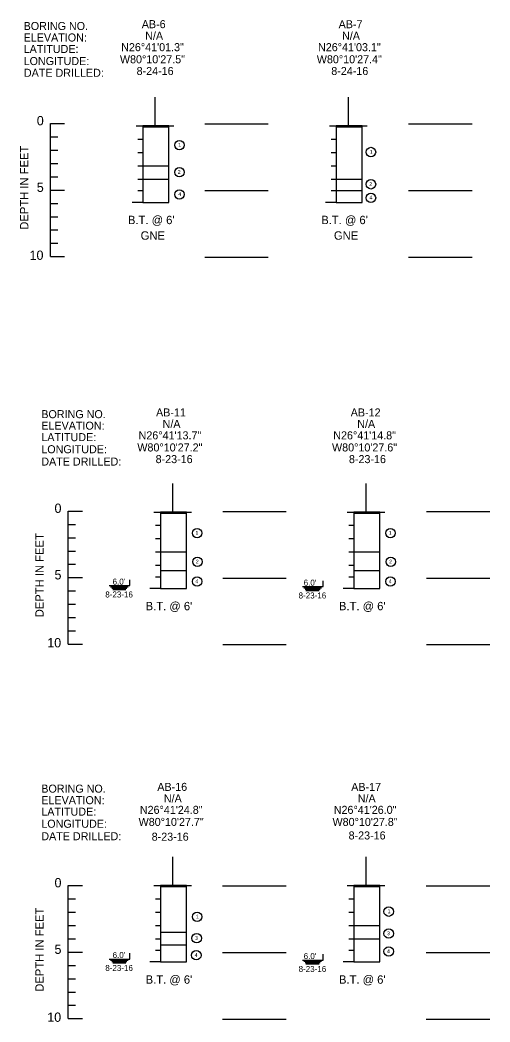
# Model space of a CAD drawing. Extents: x 0 to 331, y -72 to 117.
# Drawn here: x 74.02 to 92.94, y -21.91 to 18.43 of the extents above; entities that cross this region are included whole.
import ezdxf

# ---------------------------------------------------------------- set-up
doc = ezdxf.new("R2010")
doc.units = 0
for name, color, linetype in [('1-BORE', 7, 'Continuous'), ('1-GRID', 7, 'Continuous'), ('1-TEXT', 7, 'Continuous')]:
    doc.layers.add(name, color=color, linetype=linetype)

msp = doc.modelspace()

# ---------------------------------------------------------------- linework, layer by layer
at = {"layer": '1-BORE'}
for p, q in [((78.97, 14.122), (80.015, 14.122)), ((86.75, 14.122), (87.795, 14.122)), ((78.97, 12.556), (80.015, 12.556)), ((78.97, 12.556), (80.015, 12.556)), ((78.97, 12.02), (80.015, 12.02)), ((78.97, 12.02), (80.015, 12.02)), ((86.75, 12.02), (87.795, 12.02)), ((86.75, 12.02), (87.795, 12.02)), ((86.75, 11.557), (87.795, 11.557)), ((86.75, 11.557), (87.795, 11.557)), ((78.97, 11.083), (78.541, 11.083)), ((78.97, 11.083), (80.015, 11.083)), ((86.75, 11.083), (86.322, 11.083)), ((86.75, 11.083), (87.795, 11.083)), ((79.682, -1.422), (80.727, -1.422)), ((87.462, -1.422), (88.507, -1.422)), ((79.682, -2.989), (80.727, -2.989)), ((79.682, -2.989), (80.727, -2.989)), ((87.462, -2.989), (88.507, -2.989)), ((87.462, -2.989), (88.507, -2.989)), ((79.682, -3.739), (80.727, -3.739)), ((79.682, -3.739), (80.727, -3.739)), ((87.462, -3.739), (88.507, -3.739)), ((87.462, -3.739), (88.507, -3.739)), ((79.682, -4.462), (79.254, -4.462)), ((79.682, -4.462), (80.727, -4.462)), ((87.462, -4.462), (87.034, -4.462)), ((87.462, -4.462), (88.507, -4.462)), ((79.682, -16.459), (80.727, -16.459)), ((87.462, -16.459), (88.507, -16.459)), ((87.462, -18.025), (88.507, -18.025)), ((87.462, -18.025), (88.507, -18.025)), ((79.682, -18.3), (80.727, -18.3)), ((79.682, -18.3), (80.727, -18.3)), ((79.682, -18.802), (80.727, -18.802)), ((79.682, -18.802), (80.727, -18.802)), ((87.462, -18.561), (88.507, -18.561)), ((87.462, -18.561), (88.507, -18.561)), ((79.682, -19.498), (79.254, -19.498)), ((79.682, -19.498), (80.727, -19.498)), ((87.462, -19.498), (87.034, -19.498)), ((87.462, -19.498), (88.507, -19.498))]:
    msp.add_line(p, q, dxfattribs=at)
for points in [[(80.015, 14.122), (80.015, 14.164), (78.97, 14.164), (78.97, 14.122), (80.015, 14.122), (80.015, 14.122)], [(80.015, 11.083), (80.015, 14.164), (78.97, 14.164), (78.97, 11.083)], [(87.795, 14.122), (87.795, 14.164), (86.75, 14.164), (86.75, 14.122), (87.795, 14.122), (87.795, 14.122)], [(87.795, 11.083), (87.795, 14.164), (86.75, 14.164), (86.75, 11.083)], [(80.727, -4.462), (80.727, -1.381), (79.682, -1.381), (79.682, -4.462)], [(80.727, -1.422), (80.727, -1.381), (79.682, -1.381), (79.682, -1.422), (80.727, -1.422), (80.727, -1.422)], [(88.507, -4.462), (88.507, -1.381), (87.462, -1.381), (87.462, -4.462)], [(88.507, -1.422), (88.507, -1.381), (87.462, -1.381), (87.462, -1.422), (88.507, -1.422), (88.507, -1.422)], [(80.727, -19.498), (80.727, -16.418), (79.682, -16.418), (79.682, -19.498)], [(80.727, -16.459), (80.727, -16.418), (79.682, -16.418), (79.682, -16.459), (80.727, -16.459), (80.727, -16.459)], [(88.507, -19.498), (88.507, -16.418), (87.462, -16.418), (87.462, -19.498)], [(88.507, -16.459), (88.507, -16.418), (87.462, -16.418), (87.462, -16.459), (88.507, -16.459), (88.507, -16.459)]]:
    msp.add_lwpolyline(points, dxfattribs=at)
at = {"layer": '1-GRID'}
for p, q in [((75.254, 14.259), (75.819, 14.259)), ((81.462, 14.241), (84.016, 14.241)), ((89.662, 14.241), (92.216, 14.241)), ((75.254, 13.724), (75.539, 13.724)), ((78.765, 13.628), (78.97, 13.628)), ((86.545, 13.628), (86.75, 13.628)), ((75.254, 13.188), (75.539, 13.188)), ((78.765, 13.092), (78.97, 13.092)), ((86.545, 13.092), (86.75, 13.092)), ((75.254, 12.652), (75.539, 12.652)), ((78.765, 12.556), (78.97, 12.556)), ((86.545, 12.556), (86.75, 12.556)), ((75.254, 12.116), (75.539, 12.116)), ((78.765, 12.02), (78.97, 12.02)), ((86.545, 12.02), (86.75, 12.02)), ((75.254, 11.58), (75.819, 11.58)), ((75.254, 11.58), (75.819, 11.58)), ((78.765, 11.557), (78.97, 11.557)), ((81.462, 11.562), (84.016, 11.562)), ((86.545, 11.557), (86.75, 11.557)), ((89.662, 11.562), (92.216, 11.562)), ((75.254, 11.044), (75.539, 11.044)), ((78.97, 11.083), (79.174, 11.083)), ((86.75, 11.083), (86.955, 11.083)), ((75.254, 10.508), (75.539, 10.508)), ((75.254, 9.973), (75.539, 9.973)), ((75.254, 9.437), (75.539, 9.437)), ((75.254, 8.901), (75.819, 8.901)), ((81.462, 8.882), (84.016, 8.882)), ((89.662, 8.882), (92.216, 8.882)), ((75.966, -1.344), (76.531, -1.344)), ((75.966, -1.344), (76.531, -1.344)), ((82.183, -1.362), (84.737, -1.362)), ((90.384, -1.362), (92.938, -1.362)), ((75.966, -1.88), (76.251, -1.88)), ((79.477, -1.917), (79.682, -1.917)), ((87.258, -1.917), (87.462, -1.917)), ((75.966, -2.416), (76.251, -2.416)), ((79.477, -2.453), (79.682, -2.453)), ((87.258, -2.453), (87.462, -2.453)), ((75.966, -2.952), (76.251, -2.952)), ((79.477, -2.989), (79.682, -2.989)), ((87.258, -2.989), (87.462, -2.989)), ((75.966, -3.487), (76.251, -3.487)), ((79.477, -3.525), (79.682, -3.525)), ((87.258, -3.525), (87.462, -3.525)), ((75.966, -4.023), (76.531, -4.023)), ((75.966, -4.023), (76.531, -4.023)), ((79.477, -3.988), (79.682, -3.988)), ((87.258, -3.988), (87.462, -3.988)), ((82.183, -4.042), (84.737, -4.042)), ((90.384, -4.042), (92.938, -4.042)), ((75.966, -4.559), (76.251, -4.559)), ((79.682, -4.462), (79.887, -4.462)), ((87.462, -4.462), (87.667, -4.462)), ((75.966, -5.095), (76.251, -5.095)), ((75.966, -5.631), (76.251, -5.631)), ((75.966, -6.167), (76.251, -6.167)), ((75.966, -6.703), (76.531, -6.703)), ((82.183, -6.721), (84.737, -6.721)), ((90.384, -6.721), (92.938, -6.721)), ((75.966, -16.419), (76.531, -16.419)), ((75.966, -16.419), (76.531, -16.419)), ((82.175, -16.437), (84.729, -16.437)), ((90.374, -16.437), (92.928, -16.437)), ((75.966, -16.955), (76.251, -16.955)), ((79.477, -16.954), (79.682, -16.954)), ((87.258, -16.954), (87.462, -16.954)), ((75.966, -17.491), (76.251, -17.491)), ((79.477, -17.489), (79.682, -17.489)), ((87.258, -17.489), (87.462, -17.489)), ((75.966, -18.026), (76.251, -18.026)), ((79.477, -18.025), (79.682, -18.025)), ((87.258, -18.025), (87.462, -18.025)), ((75.966, -18.562), (76.251, -18.562)), ((79.477, -18.561), (79.682, -18.561)), ((87.258, -18.561), (87.462, -18.561)), ((75.966, -19.098), (76.531, -19.098)), ((75.966, -19.098), (76.531, -19.098)), ((79.477, -19.024), (79.682, -19.024)), ((82.175, -19.116), (84.729, -19.116)), ((87.258, -19.024), (87.462, -19.024)), ((90.374, -19.116), (92.928, -19.116)), ((75.966, -19.634), (76.251, -19.634)), ((79.682, -19.498), (79.887, -19.498)), ((87.462, -19.498), (87.667, -19.498)), ((75.966, -20.17), (76.251, -20.17)), ((75.966, -20.706), (76.251, -20.706)), ((75.966, -21.242), (76.251, -21.242)), ((75.966, -21.777), (76.531, -21.777)), ((82.175, -21.796), (84.729, -21.796)), ((90.374, -21.796), (92.928, -21.796))]:
    msp.add_line(p, q, dxfattribs=at)
for points in [[(75.254, 11.58), (75.254, 14.259)], [(75.254, 8.901), (75.254, 11.58)], [(75.966, -4.023), (75.966, -1.344)], [(75.966, -6.703), (75.966, -4.023)], [(75.966, -19.098), (75.966, -16.419)], [(75.966, -21.777), (75.966, -19.098)]]:
    msp.add_lwpolyline(points, dxfattribs=at)
at = {"layer": '1-TEXT'}
for p, q in [((79.449, 15.314), (79.449, 14.164)), ((87.23, 15.314), (87.23, 14.164)), ((80.162, -0.23), (80.162, -1.381)), ((87.942, -0.23), (87.942, -1.381)), ((77.612, -4.343), (78.437, -4.343)), ((77.666, -4.392), (78.376, -4.392)), ((78.437, -4.343), (78.437, -4.107)), ((85.392, -4.384), (86.218, -4.384)), ((85.447, -4.433), (86.157, -4.433)), ((86.218, -4.384), (86.218, -4.148)), ((77.714, -4.441), (78.32, -4.441)), ((77.752, -4.5), (78.277, -4.5)), ((85.494, -4.481), (86.101, -4.481)), ((85.533, -4.54), (86.057, -4.54)), ((80.162, -15.267), (80.162, -16.418)), ((87.942, -15.267), (87.942, -16.418)), ((78.437, -19.379), (78.437, -19.143)), ((86.218, -19.42), (86.218, -19.184)), ((77.612, -19.379), (78.437, -19.379)), ((77.666, -19.428), (78.376, -19.428)), ((77.714, -19.477), (78.32, -19.477)), ((77.752, -19.536), (78.277, -19.536)), ((85.392, -19.42), (86.218, -19.42)), ((85.447, -19.469), (86.157, -19.469)), ((85.494, -19.518), (86.101, -19.518)), ((85.533, -19.577), (86.057, -19.577))]:
    msp.add_line(p, q, dxfattribs=at)
for points in [[(78.703, 14.164), (80.212, 14.164)], [(86.484, 14.164), (87.993, 14.164)], [(79.415, -1.381), (80.925, -1.381)], [(87.196, -1.381), (88.705, -1.381)], [(79.415, -16.418), (80.925, -16.418)], [(87.196, -16.418), (88.705, -16.418)]]:
    msp.add_lwpolyline(points, dxfattribs=at)
for centre in [(80.438, 13.389), (88.149, 13.111), (80.438, 12.299), (88.149, 11.813), (80.438, 11.406), (88.149, 11.267), (81.151, -2.23), (88.931, -2.23), (81.165, -3.385), (88.946, -3.385), (81.151, -4.179), (88.931, -4.179), (88.861, -17.471), (81.151, -17.676), (81.133, -18.539), (88.861, -18.351), (88.861, -19.074), (81.119, -19.226)]:
    msp.add_circle(centre, 0.19, dxfattribs=at)

# ---------------------------------------------------------------- texts
at = {"layer": '1-GRID'}
for s, height, p in [('0', 0.375, (74.699, 14.187)), ('5', 0.375, (74.699, 11.507)), ('10', 0.3751, (74.408, 8.771)), ('0', 0.375, (75.412, -1.417)), ('5', 0.375, (75.412, -4.096)), ('10', 0.3751, (75.12, -6.832)), ('0', 0.375, (75.412, -16.492)), ('5', 0.375, (75.412, -19.171)), ('10', 0.3751, (75.12, -21.907))]:
    msp.add_text(s, height=height, dxfattribs=at).set_placement(p)
for p in [(74.361, 9.983), (74.975, -5.62), (74.975, -20.695)]:
    msp.add_text('DEPTH IN FEET', height=0.3376, rotation=90, dxfattribs=at).set_placement(p)
at = {"layer": '1-TEXT'}
for s, height, p in [('BORING NO.', 0.3231, (74.168, 18.025)), ('AB-6', 0.3231, (78.923, 18.098)), ('AB-7', 0.3231, (86.847, 18.096)), ('ELEVATION:', 0.3231, (74.168, 17.561)), ('N/A', 0.3231, (79.061, 17.632)), ('N/A', 0.3231, (86.985, 17.632)), ('LATITUDE:', 0.3231, (74.168, 17.099)), ('N26%%D41\'01.3"', 0.32313, (78.094, 17.172)), ('N26%%D41\'03.1"', 0.32313, (86.018, 17.172)), ('W80%%D10\'27.5"', 0.32313, (78.044, 16.685)), ('W80%%D10\'27.4"', 0.32313, (85.968, 16.685)), ('LONGITUDE:', 0.3231, (74.168, 16.613)), ('8-24-16', 0.3231, (78.716, 16.212)), ('8-24-16', 0.3231, (86.551, 16.212)), ('DATE DRILLED:', 0.32313, (74.179, 16.14)), ('1', 0.152, (80.393, 13.327)), ('1', 0.152, (88.103, 13.048)), ('2', 0.152, (80.37, 12.231)), ('2', 0.152, (88.081, 11.745)), ('4', 0.152, (80.393, 11.343)), ('4', 0.152, (88.087, 11.205)), ("B.T. @ 6'", 0.3376, (78.368, 10.208)), ("B.T. @ 6'", 0.3376, (86.148, 10.208)), ('GNE', 0.3376, (78.877, 9.582)), ('GNE', 0.3376, (86.657, 9.582)), ('BORING NO.', 0.3231, (74.88, 2.397)), ('AB-11', 0.3231, (79.498, 2.466)), ('AB-12', 0.3231, (87.334, 2.466)), ('ELEVATION:', 0.3231, (74.88, 1.933)), ('N/A', 0.3231, (79.762, 2.003)), ('N/A', 0.3231, (87.597, 2.003)), ('LATITUDE:', 0.3231, (74.88, 1.471)), ('N26%%D41\'13.7"', 0.32313, (78.795, 1.543)), ('N26%%D41\'14.8"', 0.32313, (86.631, 1.543)), ('LONGITUDE:', 0.3231, (74.88, 0.984)), ('W80%%D10\'27.2"', 0.32313, (78.745, 1.057)), ('W80%%D10\'27.6"', 0.32313, (86.581, 1.057)), ('DATE DRILLED:', 0.32313, (74.88, 0.489)), ('8-23-16', 0.3231, (79.481, 0.587)), ('8-23-16', 0.3231, (87.262, 0.587)), ('1', 0.152, (81.086, -2.293)), ('1', 0.152, (88.866, -2.293)), ('2', 0.152, (81.097, -3.454)), ('2', 0.152, (88.878, -3.454)), ("  6.0'", 0.2411, (77.571, -4.304)), ('4', 0.152, (81.082, -4.247)), (" 6.0'", 0.2411, (85.351, -4.345)), ('4', 0.152, (88.863, -4.247)), ('8-23-16', 0.2411, (77.455, -4.822)), ('8-23-16', 0.2411, (85.236, -4.862)), ("B.T. @ 6'", 0.3376, (79.08, -5.337)), ("B.T. @ 6'", 0.3376, (86.861, -5.337)), ('BORING NO.', 0.3231, (74.88, -12.68)), ('AB-16', 0.3231, (79.549, -12.608)), ('AB-17', 0.3231, (87.354, -12.611)), ('ELEVATION:', 0.3231, (74.88, -13.144)), ('N/A', 0.3231, (79.813, -13.074)), ('N/A', 0.3231, (87.617, -13.074)), ('LATITUDE:', 0.3231, (74.88, -13.606)), ('N26%%D41\'24.8"', 0.32313, (78.846, -13.534)), ('N26%%D41\'26.0"', 0.32313, (86.651, -13.534)), ('W80%%D10\'27.7"', 0.32313, (78.796, -14.02)), ('W80%%D10\'27.8"', 0.32313, (86.601, -14.02)), ('LONGITUDE:', 0.3231, (74.88, -14.093)), ('DATE DRILLED:', 0.32313, (74.88, -14.596)), ('8-23-16', 0.3231, (79.322, -14.615)), ('8-23-16', 0.3231, (87.248, -14.564)), ('1', 0.152, (81.105, -17.738)), ('1', 0.152, (88.815, -17.533)), ('3', 0.152, (81.065, -18.607)), ('3', 0.152, (88.793, -18.419)), ("  6.0'", 0.2411, (77.571, -19.34)), ('4', 0.152, (81.051, -19.294)), (" 6.0'", 0.2411, (85.351, -19.381)), ('4', 0.152, (88.793, -19.142)), ('8-23-16', 0.2411, (77.455, -19.858)), ('8-23-16', 0.2411, (85.236, -19.899)), ("B.T. @ 6'", 0.3376, (79.08, -20.373)), ("B.T. @ 6'", 0.3376, (86.861, -20.373))]:
    msp.add_text(s, height=height, dxfattribs=at).set_placement(p)

doc.saveas('drawing.dxf')
